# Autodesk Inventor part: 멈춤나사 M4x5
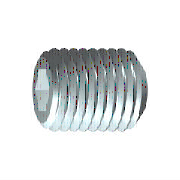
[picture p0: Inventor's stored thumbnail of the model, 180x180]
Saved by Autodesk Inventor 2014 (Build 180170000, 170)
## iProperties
Created: 2012-02
Part Number: 멈춤나사 M4x5
Material: 강철, 연강
Description: 6각 소켓 머리 없는 멈춤 나사
Document SubType Name: Modeling
Standard: KS B 1028
Designer: mduedu
Standards Organization: KS
Language: ko-KR
Size Designation: 납작점M4x5
Categories: <MemberInstance><Categories><Category DisplayName="조임쇠" InternalName="e4da775c-781d-43d5-af7c-5136215cf5a6" Mnemonic="FSTN"><Category DisplayName="볼트" InternalN
Density: 1 g/cm^3
Appearance: 강철
IsCustomPart: 1
Author: mduedu
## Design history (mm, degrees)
sketch "스케치1"
  geometry: L1 (0, 0)-(1.833, 0); L2 (5, 1.155)-(5, 2); L3 (5, 2)-(0, 2); L4 (5, 1.155)-(2.5, 1.155); L5 (2.5, 1.155)-(1.833, 0); L6 (0, -0.4)-(0, 2.4) reference; L7 (0, 2)-(0, 0)
  constraints: 13 end point, 3 parallel, 1 collinear, 1 perpendicular, 1 point on line
  dimensions: "d0" = 2.5 distance of L2.start L4.end (= INTI); "d1" = 60 deg angle of L5 L1; "d2" = 4 diameter of L3 L1 (= NND); "d3" = 2.3094 diameter of L4 L1 (= 1.1547 x SW); "d5" = 5 distance from line of L2 L3.end (= NLG)
revolve "본체" sketch "스케치1" stored, may be unused: angle "d6" = 90 deg
sketch "스케치2"
  geometry: L1 (-0.577, 1)-(0.577, 1); L2 (0.577, 1)-(1.155, 0); L3 (1.155, 0)-(0.577, -1); L4 (0.577, -1)-(-0.577, -1); L5 (-0.577, -1)-(-1.155, 0); L6 (-1.155, 0)-(-0.577, 1); A1 r 1.155 centre (0, 0) between (-0.577, 1) and (0.577, 1) reference; 2 further points
  constraints: 12 end point, 2 point on circle, 1 coincident, 1 horizontal, 11 other
extrude "슬롯" join sketch "스케치2" taper "d9" = 0 deg; stored distance "d21" = 10
workaxis "Work Axis1"
workplane "Work Plane1"
body "Solid1"
chamfer "모따기1" distance "d7" = 0.42941 (= -0.5 x GD1 + 0.5 x NND); stored, may be unused: angle "d8" = 45 deg (= FAWI), second distance "d29" = 0.42941 (= -0.5 x GD1 + 0.5 x NND)
feature "스레드" dims "d11" = 5 (= NLG), "d12" = 0
chamfer "모따기2" distance "d13" = 0.42941 (= -0.5 x GD1 + 0.5 x NND); stored, may be unused: angle "d14" = 45 deg (= FAWI), second distance "d30" = 0.42941 (= -0.5 x GD1 + 0.5 x NND)
other parameters: "NND" = 4 [user parameter; used in 5 equation terms], "NLG" = 5 [user parameter; used in 2 equation terms], "INTI" = 2.5 [user parameter; used in 1 equation term], "FAWI" = 45 deg [user parameter; used in 2 equation terms], "SW" = 2 [user parameter; used in 2 equation terms], "GD1" = 3.14117 (= THREADDIA - 1.2269 x PTC) [user parameter; used in 4 equation terms], "d4" = 0, "FAWI1" = 45 deg [user parameter], "d15" = 0, "d31" = 0, "GUL" = 0.42941 (= 0.61345 x PTC) [user parameter], "SPD" = 2.5 [user parameter], "TPU" = 14.28571 (computed from PTC) [user parameter], "TOA" = 30 deg [user parameter], "THREADDIA" = 4 [user parameter; used in 1 equation term], "PTC" = 0.7 [user parameter; used in 4 equation terms], "GAL" = 0.42941 (= 0.61345 x PTC) [user parameter], "E0" = 2.31 (= 1.155 x SW) [user parameter]
